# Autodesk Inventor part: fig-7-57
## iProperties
Shininess: 77.0
Length Units: 11269
Angle Units: 11279
Time Units: 11290
Mass Units: 11283
Length Display Precision: 3
Angle Display Precision: 2
Created: 2002-01
Part Number: fig-7-57
Document SubType Name: Modeling
Designer: ***
Density: 0.0
Volumn: 0.0
Area: 0.0
PropertySet Name: Model Information
Control State: 0
Master: False
Checked Out: False
Author: ***
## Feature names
1. Sweep1
